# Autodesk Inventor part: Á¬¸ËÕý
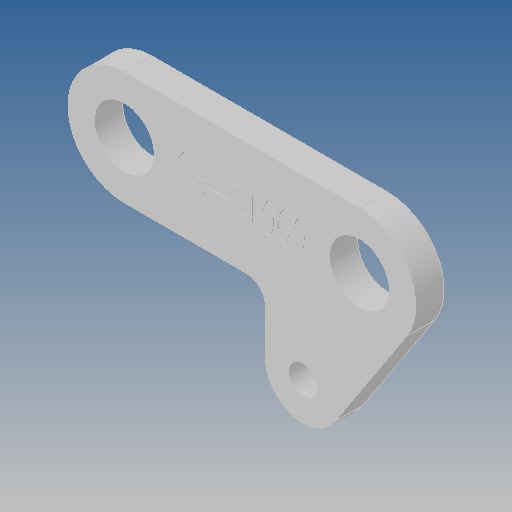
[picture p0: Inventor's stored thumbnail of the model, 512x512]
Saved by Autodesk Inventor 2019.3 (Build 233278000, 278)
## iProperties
Created: 2017-12
Part Number: Á¬¸ËÕý
Material: Ogólny
Document SubType Name: Modeling
Designer: Admin
Density: 1 g/cm^3
Appearance: Domyślna
Author: Admin
Revision Number: ÈÎºÎ
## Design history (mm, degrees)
feature "°ü¸²1"
node "Bryła1"
